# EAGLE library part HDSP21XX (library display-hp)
LED DISPLAY 8-character dot matrix
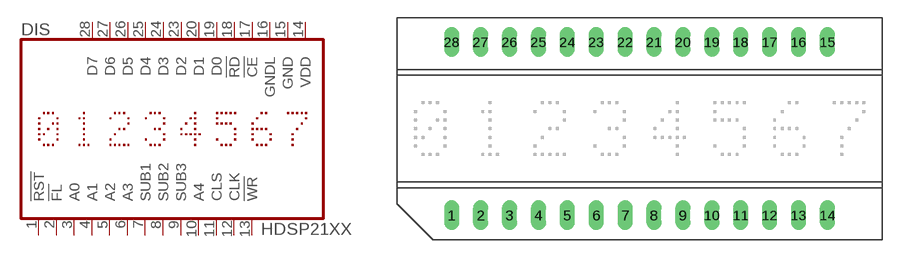
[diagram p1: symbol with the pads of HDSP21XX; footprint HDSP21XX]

Designator prefix DIS

## HDSP21XX (MF: AGILENT TECHNOLOGIES; MPN: HDSP-2179; OC_FARNELL: 1175588; OC_NEWARK: 06B1344)  [HDSP21XX]
1  !RST  in
2  !FL  in
3  A0  in
4  A1  in
5  A2  in
6  A3  in
7  SUB1  pas
8  SUB2  pas
9  SUB3  pas
10  A4  in
11  CLS  in
12  CLK  in
13  !WR  in
14  VDD  pwr
15  GND  pwr
16  GNDL  pwr
17  !CE  in
18  !RD  in
19  D0  in
20  D1  in
23  D2  in
24  D3  in
25  D4  in
26  D5  in
27  D6  in
28  D7  in

## Footprint HDSP21XX (pad centres in mm)
LED DISPLAY 5-mm 8 character dot matrix without decimal point
drill 0.813 long: 1 -16.51,-7.62; 2 -13.97,-7.62; 3 -11.43,-7.62; 4 -8.89,-7.62; 5 -6.35,-7.62; 6 -3.81,-7.62; 7 -1.27,-7.62; 8 1.27,-7.62; 9 3.81,-7.62; 10 6.35,-7.62; 11 8.89,-7.62; 12 11.43,-7.62; 13 13.97,-7.62; 14 16.51,-7.62; 15 16.51,7.62; 16 13.97,7.62; 17 11.43,7.62; 18 8.89,7.62; 19 6.35,7.62; 20 3.81,7.62; 21 1.27,7.62; 22 -1.27,7.62; 23 -3.81,7.62; 24 -6.35,7.62; 25 -8.89,7.62; 26 -11.43,7.62; 27 -13.97,7.62; 28 -16.51,7.62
